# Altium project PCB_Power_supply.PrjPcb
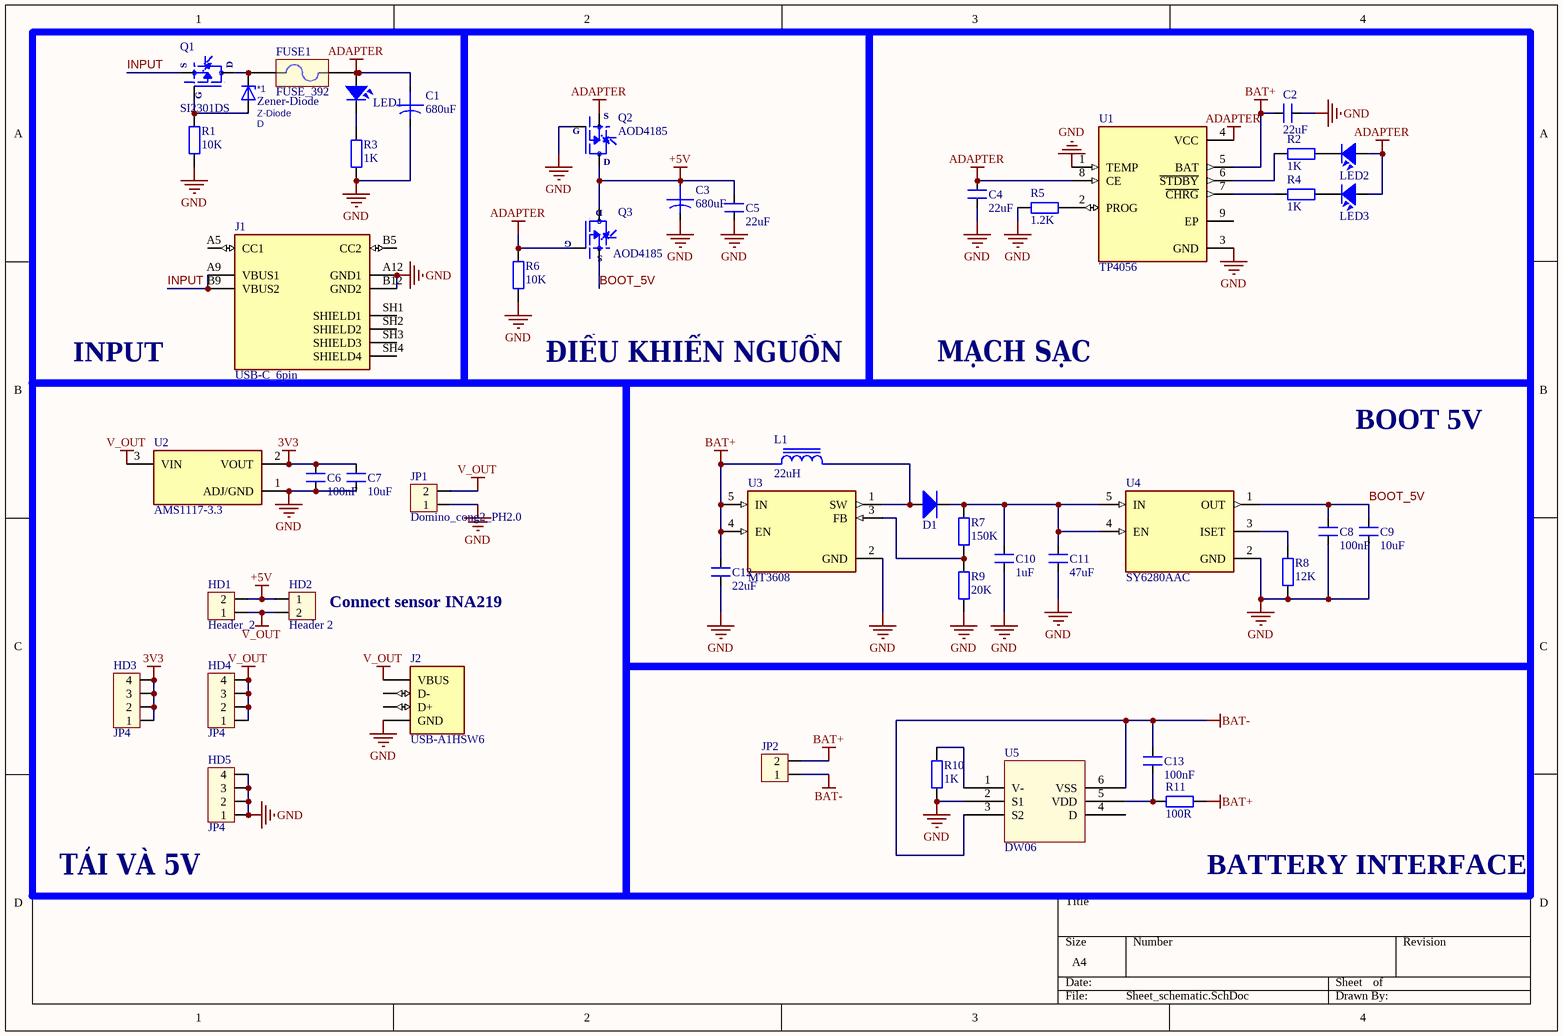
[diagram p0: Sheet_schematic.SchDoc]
1 sheet, 48 parts. Net scope: global (net labels, ports and power ports of the same name join across sheets).
Board file: PCB_layout.PcbDoc

## Sheet Sheet_schematic.SchDoc
size A4; SheetNumber: 1; SheetTotal: 1

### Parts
*1  Zener-Diode  value Z-Diode  Reference: D  [SOD-123F]
C1  680uF  [Capacitor 680uF]
C2  22uF  [C 0805]
C3  680uF  [Capacitor 680uF]
C4  22uF  [C 0805]
C5  22uF  [C 0805]
C6  100nF  [C 0805]
C7  10uF  [C 0805]
C8  100nF  [C 0805]
C9  10uF  [C 0805]
C10  1uF  [C 0805]
C11  47uF  [C 0805]
C12  22uF  [C 0805]
C13  100nF  [C 0805]
D1  Diode  [DIODE_1N4007]  (value not drawn)
FUSE1  FUSE_392  [FUSE_392]
HD1  Header_2  [HDR1X2]
HD2  Header 2  [HED2]
HD3  JP4  [HDR1X4]
HD4  JP4  [HDR1X4]
HD5  JP4  [HDR1X4]
J1  USB-C_6pin  [MOLEX_2171750001]
J2  USB-A1HSW6  [OST_USB-A1HSW6]
JP1  Domino_cong2_PH2.0  [CON2_PH2.0_Cong]
JP2  Domino_cong2_PH2.0  [CON2_PH2.0_Cong]  (value not drawn)
L1  22uH  [CDRH104R]
LED1  LED SMD  [SM-LED-0805-Red]  (value not drawn)
LED2  LED SMD  [SM-LED-0805-Green]  (value not drawn)
LED3  LED SMD  [SM-LED-0805-Red]  (value not drawn)
Q1  SI2301DS  [MOSFET_P]
Q2  AOD4185  [TO252]
Q3  AOD4185  [TO252]
R1  10K  [SM-RES-0805]
R2  1K  [SM-RES-0805]
R3  1K  [SM-RES-0805]
R4  1K  [SM-RES-0805]
R5  1.2K  [SM-RES-0805]
R6  10K  [SM-RES-0805]
R7  150K  [SM-RES-0805]
R8  12K  [SM-RES-0805]
R9  20K  [SM-RES-0805]
R10  1K  [SM-RES-0805]
R11  100R  [SM-RES-0805]
U1  TP4056  [SOP127P600X175-9N]
U2  AMS1117-3.3  [SOT229P700X180-4N]
U3  MT3608  [SOT95P280X145-6N]
U4  SY6280AAC  [SOT95P285X130-5N]
U5  DW06  [TSOT-23_S6]

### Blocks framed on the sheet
INPUT: *1 C1 FUSE1 J1 LED1 Q1 R1 R3
ĐIỀU KHIỂN NGUỒN: C3 C5 Q2 Q3 R6
MẠCH SẠC: C2 C4 LED2 LED3 R2 R4 R5 U1
TẢI VÀ 5V: C6 C7 HD1-HD5 J2 JP1 U2
BOOT 5V: C8-C12 D1 L1 R7-R9 U3 U4
BATTERY INTERFACE: C13 JP2 R10 R11 U5

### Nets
3V3: C6.2 C7.2 HD3.1 HD3.2 HD3.3 HD3.4 U2.2(VOUT)
+5V: C3.1 C5.1 HD1.2 HD2.1 Q2.3(D) Q3.3(D)
ADAPTER: C1.1 C4.2 FUSE1.2(P$2) LED1.1 LED2.1 LED3.1 Q2.2(S) Q3.1(G) R6.2 U1.4(VCC) U1.8(CE)
BAT+: C2.2 C12.2 JP2.2 L1.1 R11.1 U1.5(BAT) U3.4(EN) U3.5(IN)
BAT-: C13.2 JP2.1 U5.3(S2) U5.6(VSS)
GND: C1.2 C2.1 C3.2 C4.1 C5.2 C6.1 C7.1 C8.1 C9.1 C10.1 C11.1 C12.1 HD5.1 HD5.2 HD5.3 HD5.4 J1.A12(GND1) J1.B12(GND2) J2.4(GND) JP1.1 Q2.1(G) R1.1 R3.2 R5.2 R6.1 R8.1 R9.1 R10.2 U1.1(TEMP) U1.3(GND) U2.1(ADJ/GND) U3.2(GND) U4.2(GND) U5.2(S1)
V_OUT: HD1.1 HD2.2 HD4.1 HD4.2 HD4.3 HD4.4 J2.1(VBUS) JP1.2 U2.3(VIN)
BOOT_5V: C8.2 C9.2 Q3.2(S) U4.1(OUT)
INPUT: J1.A9(VBUS1) J1.B9(VBUS2) Q1.2(S)
Net*1_1: *1.1(K) FUSE1.1(P$1) Q1.3(D)
Net*1_2: *1.2(A) Q1.1(G) R1.2
NetC10_2: C10.2 C11.2 D1.2(K) R7.2 U4.4(EN) U4.5(IN)
NetC13_1: C13.1 R11.2 U5.5(VDD)
NetD1_1: D1.1(A) L1.2 U3.1(SW)
NetLED1_2: LED1.2 R3.1
NetLED2_2: LED2.2 R2.1
NetLED3_2: LED3.2 R4.1
NetR2_2: R2.2 U1.6(~{STDBY})
NetR4_2: R4.2 U1.7(~{CHRG})
NetR5_1: R5.1 U1.2(PROG)
NetR7_1: R7.1 R9.2 U3.3(FB)
NetR8_2: R8.2 U4.3(ISET)
NetR10_1: R10.1 U5.1(V-)

Not connected (* = marked no-connect by the designer): J1 A5(CC1) B5(CC2) SH1(SHIELD1) SH2(SHIELD2) SH3(SHIELD3) SH4(SHIELD4); J2 2(D-) 3(D+); U1 9(EP); U5 4(D)

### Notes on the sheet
- (near HD2) Connect sensor INA219

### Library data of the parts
*1 = Zener-Diode: Zener Diode, TVS-unidirectional Diode; ki_keywords: Zener TVS unidirectional Diode
C1 C3 = Cap_680uF_SMD: Cap SMD
C2 C4-C13 = CAP SMD: Value: 103
D1 = Diode_1n4007: Default Diode; Code - JEDEC: DO-214-AB; Value: 1N5007
FUSE1 = FUSE_392: Fuse Block 20A 500V 1 Circuit Blade Through Hole; MF: Keystone Electronics; MP: 3522-2
HD1 = Header_2: Connector 2.54  2 PIN
HD2 = Header_green_2pin: Header 2 (Green)
HD3-HD5 = Header_4: Connector 2.54  4 PIN; Value: Connector 4
J1 = USB-C_6pin: USB-C (USB TYPE-C) USB 2.0 Receptacle Connector 24 (6+18 Dummy) Position Surface Mount, Right Angle; Through Hole; MF: Molex; MP: 2171750001
J2 = USB-A1HSW6: MF: {'manufacturer': u'On Shore Technology Inc.'}
JP1 JP2 = Domino_cong2_PH2.0: Connector 2
L1 = INDUCTORS_CDRH104R: POWER INDUCTORS (SMD Type); MF: Sumida America Components Inc.
LED1-LED3 = LED-SMD-0805
Q1 = SI2301DS: N-Channel 50V 500mA _Ta_ 600mW _Ta_ Surface Mount SOT-23; MP: BSN20; MF: NXP Semiconductors
Q2 Q3 = AOD4185: P-Channel 40V 40A (Tc) 2.5W (Ta), 62.5W (Tc) Surface Mount TO-252, (D-Pak); MF: Alpha &
R1 R5-R9 R11 = Resistor: Resistor SMD; Value: 1K
R2-R4 R10 = Resistor: Resistor SMD
U1 = TP4056: Complete single cell Li-Ion battery with a constant current / constant voltage linear charger; MF: NanJing Top Power ASIC Corp.
U2 = AMS1117-3.3: Sot223/Pkg 1-Amp 3.3-Volt Low Drop Out Voltage Regulatator; MF: Advanced Monolithic Systems
U3 = MT3608: High Efficiency 1.2MHz2A Step Up Converter; MF: Aerosemi Technology Co., Ltd
U4 = SY6280AAC: USB Power Distribution SW Single 5.5V 1A 5-Pin SOT-23; MF: Silergy
U5 = DW06: LT1784 - 2.5MHz, Over-The-Top Low Power, Rail-to-Rail Input and Output Op Amp in SOT-23; MF: Analog Devices; MP: LT1784IS6#TR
